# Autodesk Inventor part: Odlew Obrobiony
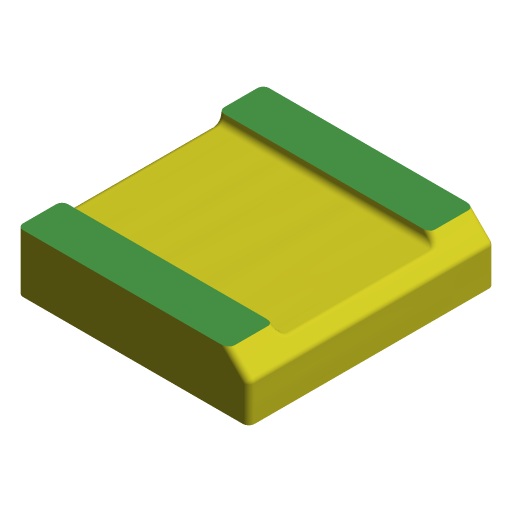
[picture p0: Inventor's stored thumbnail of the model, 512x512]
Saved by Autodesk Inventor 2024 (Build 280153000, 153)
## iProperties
Company: ATC
Shininess: 20.0
Length Units: 11269
Angle Units: 11279
Time Units: 11290
Mass Units: 11283
Length Display Precision: 3
Angle Display Precision: 2
Compacted: True
Created: 2023-03
Part Number: Odlew Obrobiony
Document SubType Name: Modeling
Designer: Andrzej Jaskulski
Material: Kurs-AJ
Density: 1 g/cm^3
Appearance: Gładki - ciemna zieleń leśna
Checked By: A.J.
Engr Approved By: Andrzej Jaskulski
Mfg Approved By: Andrzej Jaskulski
Authority: A.J.
Density: 0.0
Volumn: 0.0
Area: 0.0
PropertySet Name: Model Information
Control State: 0
Master: False
Checked Out: False
Title: A.J.: Kurs R2024-MEP
Author: Andrzej Jaskulski
Revision Number: 1/24
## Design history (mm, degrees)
derived "Odlew Surowy.ipt"
workplane "Work Plane1"
sketch "Sketch2"
  geometry: L1 (0, 85)-(76, 85) reference; L2 (78, 83)-(78, 2) reference; L3 (76, 0)-(0, 0) reference; L4 (-2, 2)-(-2, 83) reference; A1 r 2 centre (0, 83) between (0, 85) and (-2, 83) reference; A2 r 2 centre (76, 83) between (78, 83) and (76, 85) reference; A3 r 2 centre (76, 2) between (76, 0) and (78, 2) reference; A4 r 2 centre (0, 2) between (-2, 2) and (0, 0) reference
extrude "Extrusion1" cut sketch "Sketch2" extent not by distance; stored distance "d3" = 10; taper "d4" = 0 deg
node "Bryła1"
node "Korpusy bryłowe"
node "Korpusy powierzchniowe"
tag "Bryła wyprowadzona2"
feature "DerivedBody::Odlew Surowy.ipt" dims "d1" = 10
other parameters: "SZEROKOŚĆ" = 85 [user parameter], "NADDATEK" = 3 [user parameter], "PROMIEŃ" = 2 [user parameter]
